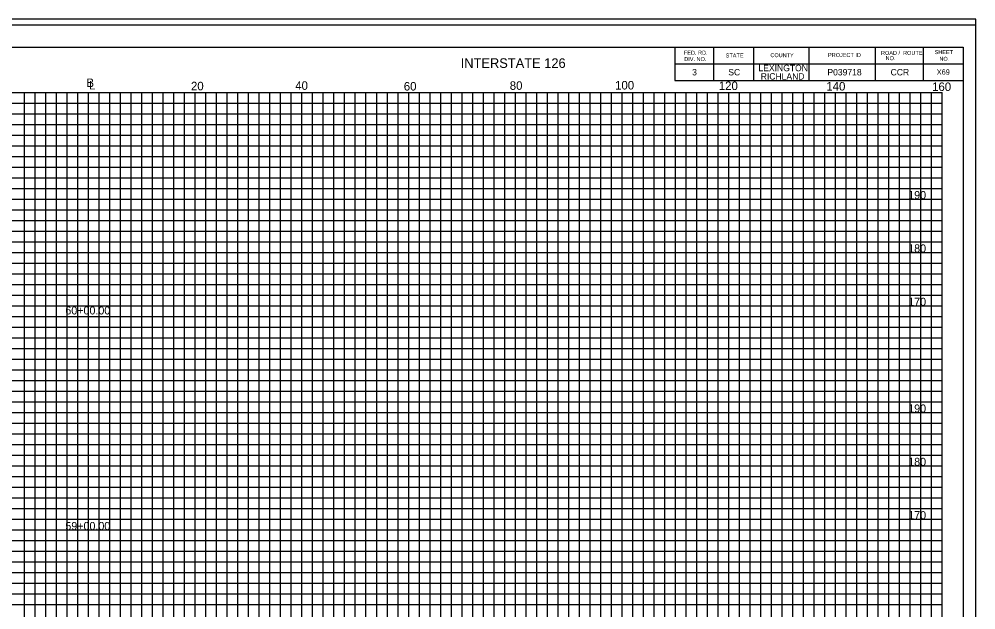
# Model space of a CAD drawing. Extents: x 967 to 1623, y 964 to 7064.
# Drawn here: x 1147 to 1326.3, y 5833 to 5943.7 of the extents above; entities that cross this region are included whole.
import ezdxf

# ---------------------------------------------------------------- set-up
doc = ezdxf.new("R2010")
doc.units = 0
for name, color, linetype in [('Default', 7, 'Continuous'), ('RD_SHT_Bndy', 7, 'Continuous'), ('RD_SHT_IplotShp', 7, 'Continuous'), ('RD_SHT_MjGrid', 7, 'Continuous'), ('RD_SHT_MnGrid', 7, 'Continuous'), ('RD_SHT_TX', 7, 'Continuous'), ('RD_Sketch1', 7, 'Continuous')]:
    doc.layers.add(name, color=color, linetype=linetype)

msp = doc.modelspace()

# ---------------------------------------------------------------- linework, layer by layer
at = {"layer": 'RD_SHT_Bndy'}
for p, q in [((996.11, 5938.46), (1323.89, 5938.46)), ((1269.89, 5938.46), (1269.89, 5932.21)), ((1277.14, 5938.46), (1277.14, 5932.21)), ((1284.64, 5938.46), (1284.64, 5932.21)), ((1295, 5938.46), (1295, 5932.21)), ((1307.43, 5938.46), (1307.43, 5932.21)), ((1316.39, 5938.46), (1316.39, 5932.21)), ((1323.89, 5938.46), (1323.89, 5728.98)), ((1269.89, 5935.33), (1323.89, 5935.33)), ((1269.89, 5932.21), (1323.89, 5932.21))]:
    msp.add_line(p, q, dxfattribs=at)
at = {"layer": 'RD_SHT_IplotShp'}
for points in [[(967.41, 5723.72), (1326.28, 5723.72), (1326.28, 5943.72), (967.41, 5943.72)], [(988.52, 5724.84), (1326.28, 5724.84), (1326.28, 5942.6), (988.52, 5942.6)]]:
    msp.add_lwpolyline(points, close=True, dxfattribs=at)
at = {"layer": 'RD_SHT_MjGrid'}
for p, q in [((1000, 5930), (1320, 5930)), ((1150, 5760), (1150, 5930)), ((1160, 5760), (1160, 5930)), ((1170, 5760), (1170, 5930)), ((1180, 5760), (1180, 5930)), ((1190, 5760), (1190, 5930)), ((1200, 5760), (1200, 5930)), ((1210, 5760), (1210, 5930)), ((1220, 5760), (1220, 5930)), ((1230, 5760), (1230, 5930)), ((1240, 5760), (1240, 5930)), ((1250, 5760), (1250, 5930)), ((1260, 5760), (1260, 5930)), ((1270, 5760), (1270, 5930)), ((1280, 5760), (1280, 5930)), ((1290, 5760), (1290, 5930)), ((1300, 5760), (1300, 5930)), ((1310, 5760), (1310, 5930)), ((1320, 5760), (1320, 5930)), ((1000, 5920), (1320, 5920)), ((1000, 5910), (1320, 5910)), ((1000, 5900), (1320, 5900)), ((1000, 5890), (1320, 5890)), ((1000, 5880), (1320, 5880)), ((1000, 5870), (1320, 5870)), ((1000, 5860), (1320, 5860)), ((1000, 5850), (1320, 5850)), ((1000, 5840), (1320, 5840))]:
    msp.add_line(p, q, dxfattribs=at)
at = {"layer": 'RD_SHT_MnGrid'}
for p, q in [((1148, 5760), (1148, 5930)), ((1152, 5760), (1152, 5930)), ((1154, 5760), (1154, 5930)), ((1156, 5760), (1156, 5930)), ((1158, 5760), (1158, 5930)), ((1162, 5760), (1162, 5930)), ((1164, 5760), (1164, 5930)), ((1166, 5760), (1166, 5930)), ((1168, 5760), (1168, 5930)), ((1172, 5760), (1172, 5930)), ((1174, 5760), (1174, 5930)), ((1176, 5760), (1176, 5930)), ((1178, 5760), (1178, 5930)), ((1182, 5760), (1182, 5930)), ((1184, 5760), (1184, 5930)), ((1186, 5760), (1186, 5930)), ((1188, 5760), (1188, 5930)), ((1192, 5760), (1192, 5930)), ((1194, 5760), (1194, 5930)), ((1196, 5760), (1196, 5930)), ((1198, 5760), (1198, 5930)), ((1202, 5760), (1202, 5930)), ((1204, 5760), (1204, 5930)), ((1206, 5760), (1206, 5930)), ((1208, 5760), (1208, 5930)), ((1212, 5760), (1212, 5930)), ((1214, 5760), (1214, 5930)), ((1216, 5760), (1216, 5930)), ((1218, 5760), (1218, 5930)), ((1222, 5760), (1222, 5930)), ((1224, 5760), (1224, 5930)), ((1226, 5760), (1226, 5930)), ((1228, 5760), (1228, 5930)), ((1232, 5760), (1232, 5930)), ((1234, 5760), (1234, 5930)), ((1236, 5760), (1236, 5930)), ((1238, 5760), (1238, 5930)), ((1242, 5760), (1242, 5930)), ((1244, 5760), (1244, 5930)), ((1246, 5760), (1246, 5930)), ((1248, 5760), (1248, 5930)), ((1252, 5760), (1252, 5930)), ((1254, 5760), (1254, 5930)), ((1256, 5760), (1256, 5930)), ((1258, 5760), (1258, 5930)), ((1262, 5760), (1262, 5930)), ((1264, 5760), (1264, 5930)), ((1266, 5760), (1266, 5930)), ((1268, 5760), (1268, 5930)), ((1272, 5760), (1272, 5930)), ((1274, 5760), (1274, 5930)), ((1276, 5760), (1276, 5930)), ((1278, 5760), (1278, 5930)), ((1282, 5760), (1282, 5930)), ((1284, 5760), (1284, 5930)), ((1286, 5760), (1286, 5930)), ((1288, 5760), (1288, 5930)), ((1292, 5760), (1292, 5930)), ((1294, 5760), (1294, 5930)), ((1296, 5760), (1296, 5930)), ((1298, 5760), (1298, 5930)), ((1302, 5760), (1302, 5930)), ((1304, 5760), (1304, 5930)), ((1306, 5760), (1306, 5930)), ((1308, 5760), (1308, 5930)), ((1312, 5760), (1312, 5930)), ((1314, 5760), (1314, 5930)), ((1316, 5760), (1316, 5930)), ((1318, 5760), (1318, 5930)), ((1000, 5928), (1320, 5928)), ((1000, 5926), (1320, 5926)), ((1000, 5924), (1320, 5924)), ((1000, 5922), (1320, 5922)), ((1000, 5918), (1320, 5918)), ((1000, 5916), (1320, 5916)), ((1000, 5914), (1320, 5914)), ((1000, 5912), (1320, 5912)), ((1000, 5908), (1320, 5908)), ((1000, 5906), (1320, 5906)), ((1000, 5904), (1320, 5904)), ((1000, 5902), (1320, 5902)), ((1000, 5898), (1320, 5898)), ((1000, 5896), (1320, 5896)), ((1000, 5894), (1320, 5894)), ((1000, 5892), (1320, 5892)), ((1000, 5888), (1320, 5888)), ((1000, 5886), (1320, 5886)), ((1000, 5884), (1320, 5884)), ((1000, 5882), (1320, 5882)), ((1000, 5878), (1320, 5878)), ((1000, 5876), (1320, 5876)), ((1000, 5874), (1320, 5874)), ((1000, 5872), (1320, 5872)), ((1000, 5868), (1320, 5868)), ((1000, 5866), (1320, 5866)), ((1000, 5864), (1320, 5864)), ((1000, 5862), (1320, 5862)), ((1000, 5858), (1320, 5858)), ((1000, 5856), (1320, 5856)), ((1000, 5854), (1320, 5854)), ((1000, 5852), (1320, 5852)), ((1000, 5848), (1320, 5848)), ((1000, 5846), (1320, 5846)), ((1000, 5844), (1320, 5844)), ((1000, 5842), (1320, 5842)), ((1000, 5838), (1320, 5838)), ((1000, 5836), (1320, 5836)), ((1000, 5834), (1320, 5834))]:
    msp.add_line(p, q, dxfattribs=at)
at = {"layer": 'RD_Sketch1'}
msp.add_lwpolyline([(967.41, 5723.72), (1326.28, 5723.72), (1326.28, 5943.72), (967.41, 5943.72)], close=True, dxfattribs=at)

# ---------------------------------------------------------------- texts
at = {"layer": 'Default'}
for s, height, p in [('X69', 1, (1318.95, 5933.3)), ('190', 1.5, (1313.61, 5910)), ('180', 1.5, (1313.61, 5900)), ('170', 1.5, (1313.61, 5890)), ('60+00.00', 1.5, (1155.66, 5888.37)), ('190', 1.5, (1313.61, 5870)), ('180', 1.5, (1313.61, 5860)), ('170', 1.5, (1313.61, 5850)), ('59+00.00', 1.5, (1155.66, 5847.97))]:
    msp.add_text(s, height=height, dxfattribs=at).set_placement(p)
at = {"layer": 'RD_SHT_TX'}
for s, height, p in [('SHEET', 0.75, (1318.56, 5937.16)), ('FED. RD.', 0.75, (1271.58, 5937.05)), ('DIV. NO.', 0.75, (1271.64, 5935.86)), ('STATE', 0.75, (1279.41, 5936.53)), ('COUNTY', 0.75, (1287.78, 5936.59)), ('PROJECT ID', 0.75, (1298.58, 5936.63)), ('ROAD /  ROUTE', 0.75, (1308.51, 5937.01)), ('   NO.', 0.75, (1308.51, 5936.03)), ('NO.', 0.75, (1319.45, 5935.91)), ('3', 1.2, (1273.12, 5933.17)), ('SC', 1.2, (1279.89, 5933.17)), ('LEXINGTON', 1.2, (1285.54, 5933.96)), ('P039718', 1.2, (1298.46, 5933.17)), ('CCR', 1.2, (1310.31, 5933.17)), ('B', 1.6, (1159.61, 5930.99)), ('RICHLAND', 1.2, (1285.97, 5932.39)), ('L', 1.6, (1160.12, 5930.54)), ('20', 1.6, (1179.2, 5930.38)), ('40', 1.6, (1198.74, 5930.47)), ('60', 1.6, (1219.08, 5930.33)), ('80', 1.6, (1238.94, 5930.47)), ('100', 1.6, (1258.67, 5930.53)), ('120', 1.6, (1278.11, 5930.43)), ('140', 1.6, (1298.26, 5930.34)), ('160', 1.6, (1318.08, 5930.25))]:
    msp.add_text(s, height=height, dxfattribs=at).set_placement(p)
msp.add_text('INTERSTATE 126 ', height=1.8, rotation=0, dxfattribs=at).set_placement((1229.75, 5934.58))

doc.saveas('drawing.dxf')
